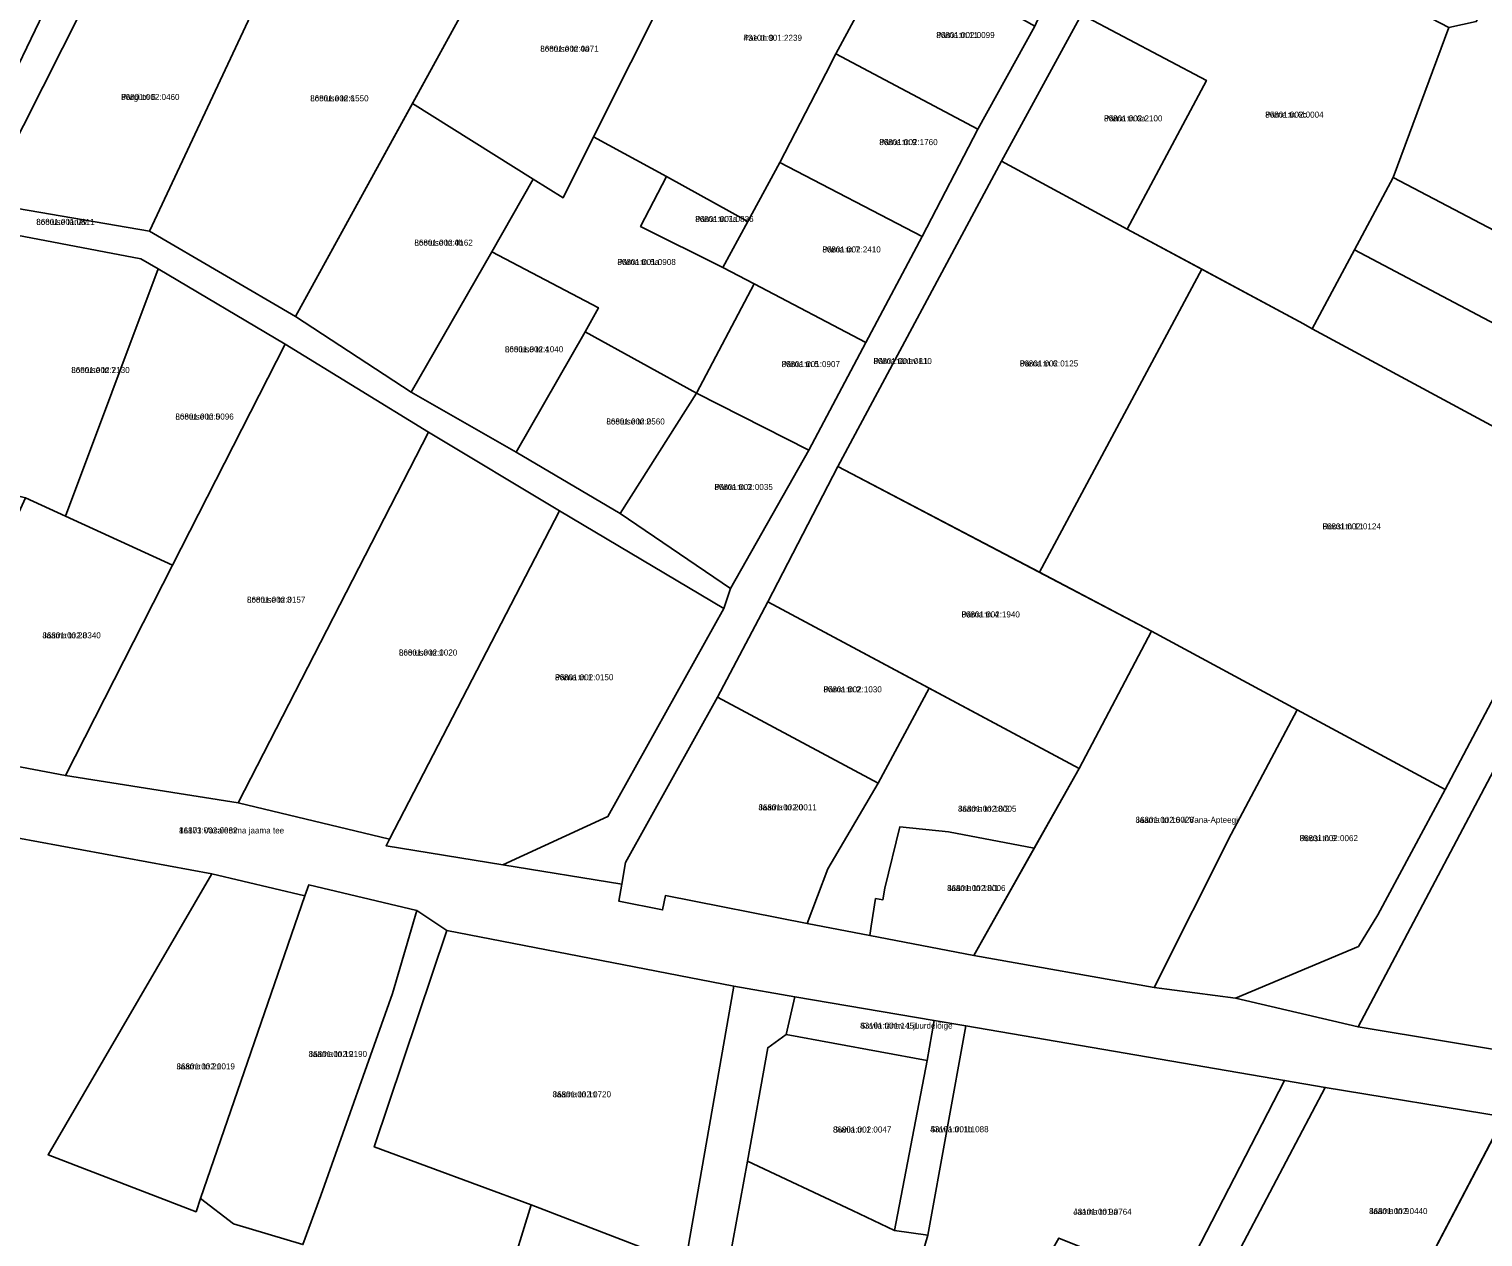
# Model space of a CAD drawing. Extents: x 484607 to 525396, y 6554521 to 6586559.
# Drawn here: x 516301.7 to 516662.8, y 6566598.8 to 6566898.8 of the extents above; entities that cross this region are included whole.
import ezdxf

# ---------------------------------------------------------------- set-up
doc = ezdxf.new("R2010")
doc.units = 0
for name, color, linetype in [('L_AADRESS', 7, 'Continuous'), ('PIIR', 7, 'Continuous'), ('TUNNUS', 7, 'Continuous')]:
    doc.layers.add(name, color=color, linetype=linetype)

msp = doc.modelspace()

# ---------------------------------------------------------------- linework, layer by layer
at = {"layer": 'PIIR'}
for points in [[(516290.5, 6566855.68), (516278.33, 6566857.98), (516282.18, 6566858.75), (516284.92, 6566860.86), (516294.91, 6566881.33), (516311.47, 6566915.84), (516310.19, 6566916.2), (516337.05, 6566972.83), (516342.42, 6566984.14), (516343.49, 6566983.98), (516389.77, 6567083.97), (516398.58, 6567080.56), (516370.04, 6567017.12), (516349.44, 6566970.95), (516343.83, 6566959.05), (516340.8, 6566952.72), (516321.97, 6566913.04), (516319.66, 6566913.38)], [(516448.91, 6566686.41), (516419.34, 6566691.2), (516445.43, 6566703.16), (516474.23, 6566754.86), (516475.84, 6566759.81), (516495.3, 6566794.2), (516509.48, 6566820.94), (516523.5, 6566847.29), (516537.33, 6566873.92), (516551.44, 6566899.57), (516554.36, 6566906.06), (516574.97, 6566943.43), (516595.7, 6566980.41), (516603.41, 6566978.18), (516581.41, 6566937.13), (516563.07, 6566902.41), (516543.2, 6566866.04), (516502.5, 6566790.15), (516485.19, 6566756.57), (516472.67, 6566732.86), (516449.84, 6566691.78)], [(516460.36, 6566909.06), (516477.5, 6566941.11), (516516.4, 6566919.26), (516502.06, 6566892.7), (516499.59, 6566887.8), (516488.12, 6566865.7), (516480.2, 6566851.03), (516460.02, 6566862.16), (516441.87, 6566872.04)], [(516581.41, 6566937.13), (516654.28, 6566899.25), (516640.42, 6566861.91), (516630.88, 6566843.96), (516620.33, 6566824.39), (516618.15, 6566825.57), (516574.43, 6566849.15), (516594.09, 6566886.06), (516563.07, 6566902.41)], [(516654.28, 6566899.25), (516661.08, 6566900.7), (516680.61, 6566937.25), (516717.24, 6566917.86), (516695.46, 6566877.12), (516677.38, 6566842.58), (516640.42, 6566861.91)], [(516367.84, 6566827.44), (516331.58, 6566848.64), (516358.56, 6566906.22), (516369.23, 6566928.83), (516411.41, 6566906.84)], [(516422.67, 6566929.08), (516460.36, 6566909.06), (516441.87, 6566872.04), (516434.28, 6566856.93), (516426.89, 6566861.56), (516396.91, 6566880.36), (516411.41, 6566906.84), (516414.41, 6566912.73)], [(516253.7, 6566891.83), (516268.99, 6566923.91), (516293.21, 6566921.02), (516310.19, 6566916.2), (516311.47, 6566915.84), (516294.91, 6566881.33)], [(516502.06, 6566892.7), (516516.4, 6566919.26), (516551.44, 6566899.57), (516537.33, 6566873.92)], [(516358.56, 6566906.22), (516331.58, 6566848.64), (516290.5, 6566855.68), (516319.66, 6566913.38), (516321.97, 6566913.04)], [(516563.07, 6566902.41), (516594.09, 6566886.06), (516574.43, 6566849.15), (516543.2, 6566866.04)], [(516631.74, 6566650.91), (516601.29, 6566658.08), (516631.85, 6566670.87), (516636.68, 6566678.77), (516653.36, 6566709.91), (516693.09, 6566785.13), (516704.24, 6566805.22), (516713.64, 6566823.3), (516727.86, 6566850.01), (516753.76, 6566898.39), (516761.08, 6566894.66), (516747.01, 6566868.16), (516727.22, 6566830.91), (516713.97, 6566805.98), (516700.94, 6566781.24), (516688.01, 6566756.39), (516674.58, 6566731.94)], [(516488.12, 6566865.7), (516499.59, 6566887.8), (516502.06, 6566892.7), (516537.33, 6566873.92), (516523.5, 6566847.29)], [(516367.84, 6566827.44), (516396.91, 6566880.36), (516426.89, 6566861.56), (516416.59, 6566843.44), (516396.6, 6566808.63)], [(516416.59, 6566843.44), (516426.89, 6566861.56), (516434.28, 6566856.93), (516441.87, 6566872.04), (516460.02, 6566862.16), (516453.53, 6566849.81), (516474.01, 6566839.61), (516481.75, 6566835.49), (516467.47, 6566808.38), (516439.76, 6566823.6), (516443.07, 6566829.59)], [(516474.01, 6566839.61), (516480.2, 6566851.03), (516488.12, 6566865.7), (516523.5, 6566847.29), (516509.48, 6566820.94), (516481.75, 6566835.49)], [(516543.2, 6566866.04), (516574.43, 6566849.15), (516592.97, 6566839.15), (516552.6, 6566763.86), (516502.5, 6566790.15)], [(516453.53, 6566849.81), (516460.02, 6566862.16), (516480.2, 6566851.03), (516474.01, 6566839.61)], [(516640.42, 6566861.91), (516677.38, 6566842.58), (516713.64, 6566823.3), (516704.24, 6566805.22), (516681.92, 6566818.43), (516678.57, 6566820.42), (516677.72, 6566818.98), (516674.54, 6566820.87), (516630.88, 6566843.96)], [(516329.39, 6566841.77), (516333.7, 6566839.22), (516310.7, 6566777.82), (516300.81, 6566782.35), (516290.6, 6566784.81), (516291.21, 6566786.89), (516292.55, 6566787.24), (516293.45, 6566791.08), (516295.36, 6566798.74), (516292.91, 6566809.24), (516293.7, 6566812.42), (516291.26, 6566813.14), (516292.58, 6566819.08), (516298.6, 6566847.64)], [(516416.59, 6566843.44), (516443.07, 6566829.59), (516439.76, 6566823.6), (516422.63, 6566793.73), (516396.6, 6566808.63)], [(516630.88, 6566843.96), (516674.54, 6566820.87), (516677.72, 6566818.98), (516678.57, 6566820.42), (516681.92, 6566818.43), (516704.24, 6566805.22), (516693.09, 6566785.13), (516620.33, 6566824.39)], [(516333.7, 6566839.22), (516365.31, 6566820.52), (516337.32, 6566765.6), (516310.7, 6566777.82)], [(516592.97, 6566839.15), (516618.15, 6566825.57), (516620.33, 6566824.39), (516693.09, 6566785.13), (516653.36, 6566709.91), (516616.63, 6566729.74), (516580.47, 6566749.24), (516552.6, 6566763.86)], [(516467.47, 6566808.38), (516481.75, 6566835.49), (516509.48, 6566820.94), (516495.3, 6566794.2)], [(516467.47, 6566808.38), (516448.48, 6566778.46), (516422.63, 6566793.73), (516439.76, 6566823.6)], [(516365.31, 6566820.52), (516400.87, 6566798.65), (516353.64, 6566706.61), (516310.71, 6566713.38), (516337.32, 6566765.6)], [(516475.84, 6566759.81), (516448.48, 6566778.46), (516467.47, 6566808.38), (516495.3, 6566794.2)], [(516400.87, 6566798.65), (516433.4, 6566779.13), (516391.18, 6566697.54), (516353.64, 6566706.61)], [(516562.46, 6566715.14), (516485.19, 6566756.57), (516502.5, 6566790.15), (516580.47, 6566749.24)], [(516337.32, 6566765.6), (516310.71, 6566713.38), (516272.63, 6566720.63), (516273.54, 6566722.61), (516300.81, 6566782.35), (516310.7, 6566777.82)], [(516474.23, 6566754.86), (516445.43, 6566703.16), (516419.34, 6566691.2), (516390.34, 6566695.92), (516391.18, 6566697.54), (516433.4, 6566779.13)], [(516485.19, 6566756.57), (516525.21, 6566735.11), (516512.53, 6566711.5), (516472.67, 6566732.86)], [(516616.63, 6566729.74), (516600.19, 6566698.81), (516581.07, 6566660.76), (516536.31, 6566668.71), (516562.46, 6566715.14), (516580.47, 6566749.24)], [(516500.06, 6566690.2), (516512.53, 6566711.5), (516525.21, 6566735.11), (516562.46, 6566715.14), (516551.32, 6566695.37), (516530, 6566699.37), (516517.95, 6566700.64), (516514.18, 6566685.42), (516513.72, 6566682.52), (516511.91, 6566682.81), (516510.81, 6566675.93), (516510.45, 6566673.67), (516494.89, 6566676.65)], [(516512.53, 6566711.5), (516500.06, 6566690.2), (516494.89, 6566676.65), (516459.71, 6566683.57), (516459.01, 6566680.01), (516448.18, 6566682.14), (516448.91, 6566686.41), (516449.84, 6566691.78), (516472.67, 6566732.86)], [(516712.86, 6566711.63), (516706.02, 6566699), (516705.26, 6566699.39), (516676.68, 6566643.47), (516631.74, 6566650.91), (516674.58, 6566731.94)], [(516616.63, 6566729.74), (516653.36, 6566709.91), (516636.68, 6566678.77), (516631.85, 6566670.87), (516601.29, 6566658.08), (516581.07, 6566660.76), (516600.19, 6566698.81)], [(516536.31, 6566668.71), (516510.45, 6566673.67), (516510.81, 6566675.93), (516511.91, 6566682.81), (516513.72, 6566682.52), (516514.18, 6566685.42), (516517.95, 6566700.64), (516530, 6566699.37), (516551.32, 6566695.37)], [(516370.19, 6566683.5), (516344.25, 6566608.32), (516343.14, 6566605.01), (516306.39, 6566619.19), (516347.09, 6566688.95)], [(516397.98, 6566679.87), (516391.91, 6566659.2), (516374.17, 6566609.04), (516369.68, 6566596.85), (516352.41, 6566602.02), (516344.25, 6566608.32), (516370.19, 6566683.5), (516371.12, 6566686.19)], [(516476.68, 6566661.02), (516464.65, 6566592.02), (516426.41, 6566606.7), (516387.41, 6566621.11), (516405.45, 6566674.88)], [(516491.88, 6566658.39), (516526.45, 6566652.51), (516524.74, 6566642.6), (516489.67, 6566649.01)], [(516534.34, 6566651.16), (516524.85, 6566599.21), (516516.62, 6566600.37), (516524.74, 6566642.6), (516526.45, 6566652.51)], [(516516.62, 6566600.37), (516506.18, 6566605.33), (516480.06, 6566617.55), (516485.11, 6566645.77), (516489.67, 6566649.01), (516524.74, 6566642.6)], [(516524.85, 6566599.21), (516534.34, 6566651.16), (516613.48, 6566637.62), (516587.11, 6566586.51), (516557.39, 6566598.45), (516553.9, 6566592.27), (516537.14, 6566560.84), (516535.6, 6566557.36), (516515.51, 6566566.91)], [(516532.44, 6566464.05), (516524.29, 6566467.04), (516565.87, 6566545.03), (516582.88, 6566576.82), (516587.11, 6566586.51), (516613.48, 6566637.62), (516623.59, 6566635.89), (516600.94, 6566592.98), (516562.86, 6566518.16), (516551.94, 6566498.86)], [(516668.04, 6566628.55), (516638.62, 6566572.52), (516600.94, 6566592.98), (516623.59, 6566635.89)], [(516715.37, 6566623.3), (516676.49, 6566552.95), (516638.62, 6566572.52), (516669.65, 6566631.63)], [(516480.06, 6566617.55), (516506.18, 6566605.33), (516516.62, 6566600.37), (516524.85, 6566599.21), (516515.51, 6566566.91), (516513.87, 6566567.67), (516476.26, 6566586.79), (516474.81, 6566587.09), (516475.56, 6566592.77)], [(516414.58, 6566568.67), (516426.41, 6566606.7), (516464.65, 6566592.02), (516458.15, 6566552.93)]]:
    msp.add_lwpolyline(points, close=True, dxfattribs=at)
for points in [[(516290.5, 6566855.68), (516331.58, 6566848.64), (516367.84, 6566827.44), (516396.6, 6566808.63), (516422.63, 6566793.73), (516448.48, 6566778.46), (516475.84, 6566759.81), (516474.23, 6566754.86), (516433.4, 6566779.13), (516400.87, 6566798.65), (516365.31, 6566820.52), (516333.7, 6566839.22), (516329.39, 6566841.77), (516298.6, 6566847.64)], [(516272.63, 6566720.63), (516310.71, 6566713.38), (516353.64, 6566706.61), (516391.18, 6566697.54), (516390.34, 6566695.92), (516419.34, 6566691.2), (516448.91, 6566686.41), (516448.18, 6566682.14), (516459.01, 6566680.01), (516459.71, 6566683.57), (516494.89, 6566676.65), (516510.45, 6566673.67), (516536.31, 6566668.71), (516581.07, 6566660.76), (516601.29, 6566658.08), (516631.74, 6566650.91), (516676.68, 6566643.47)], [(516841.78, 6566597.63), (516812.41, 6566603.04), (516800.32, 6566605.27), (516714.17, 6566621.13), (516715.37, 6566623.3), (516669.65, 6566631.63), (516668.04, 6566628.55), (516623.59, 6566635.89), (516613.48, 6566637.62), (516534.34, 6566651.16), (516526.45, 6566652.51), (516491.88, 6566658.39), (516476.68, 6566661.02), (516405.45, 6566674.88), (516397.98, 6566679.87), (516371.12, 6566686.19), (516370.19, 6566683.5), (516347.09, 6566688.95), (516287.75, 6566699.91)], [(516287.75, 6566699.91), (516347.09, 6566688.95), (516306.39, 6566619.19), (516343.14, 6566605.01), (516344.25, 6566608.32), (516352.41, 6566602.02), (516369.68, 6566596.85), (516374.17, 6566609.04), (516391.91, 6566659.2), (516397.98, 6566679.87), (516405.45, 6566674.88), (516387.41, 6566621.11), (516426.41, 6566606.7), (516414.58, 6566568.67), (516401.53, 6566528.92), (516381.14, 6566533.25), (516367.98, 6566553.24), (516323.18, 6566539.6), (516323.16, 6566533.18), (516288.85, 6566519.72)], [(516464.65, 6566592.02), (516476.68, 6566661.02), (516491.88, 6566658.39), (516489.67, 6566649.01), (516485.11, 6566645.77), (516480.06, 6566617.55), (516475.56, 6566592.77)]]:
    msp.add_lwpolyline(points, dxfattribs=at)

# ---------------------------------------------------------------- texts
at = {"layer": 'L_AADRESS'}
for s, p in [('Pae tn 9', (516479.13, 6566895.9)), ('Pärna tn 11', (516526.98, 6566896.59)), ('Lootuse tn 4a', (516428.63, 6566893.19)), ('Pargi tn 6', (516324.53, 6566881.21)), ('Lootuse tn 6', (516371.49, 6566880.87)), ('Pärna tn 6a', (516568.65, 6566875.88)), ('Pärna tn 6b', (516608.68, 6566876.82)), ('Pärna tn 9', (516512.82, 6566869.99)), ('Lootuse tänav', (516303.45, 6566850.17)), ('Pärna tn 7a', (516467.11, 6566850.88)), ('Lootuse tn 4b', (516397.37, 6566845.02)), ('Pärna tn 7', (516498.7, 6566843.32)), ('Pärna tn 5a', (516447.79, 6566840.21)), ('Lootuse tn 4', (516419.84, 6566818.54)), ('Lootuse tn 7', (516312.15, 6566813.37)), ('Pärna tn 5', (516488.56, 6566814.84)), ('Pärna tänav L1', (516511.38, 6566815.6)), ('Pärna tn 6', (516547.73, 6566815)), ('Lootuse tn 5', (516338.01, 6566801.81)), ('Lootuse tn 2', (516445.05, 6566800.59)), ('Pärna tn 3', (516471.89, 6566784.32)), ('Roosi tn 11', (516622.91, 6566774.53)), ('Lootuse tn 3', (516355.79, 6566756.32)), ('Pärna tn 4', (516533.25, 6566752.65)), ('Jaama tn 28', (516304.98, 6566747.46)), ('Lootuse tn 1', (516393.52, 6566743.19)), ('Pärna tn 1', (516432.29, 6566737.05)), ('Pärna tn 2', (516498.96, 6566734.04)), ('Jaama tn 20', (516482.82, 6566704.75)), ('Jaama tn 18/2', (516532.39, 6566704.39)), ('Jaama tn 16 // Vana-Apteegi', (516576.47, 6566701.62)), ('11173 Vasalemma jaama tee', (516338.93, 6566698.99)), ('Roosi tn 9', (516617.21, 6566697.08)), ('Jaama tn 18/1', (516529.68, 6566684.68)), ('Suvila tänav 1 juurdelõige', (516508.06, 6566650.5)), ('Jaama tn 19', (516371.11, 6566643.46)), ('Jaama tn 21', (516338.29, 6566640.37)), ('Jaama tn 11', (516431.71, 6566633.45)), ('Suvila tn 1b', (516525.48, 6566624.77)), ('Suvila tn 1', (516501.32, 6566624.69)), ('Jaama tn 9a', (516561.02, 6566604.26)), ('Jaama tn 9', (516634.49, 6566604.43))]:
    msp.add_text(s, height=1.5, dxfattribs=at).set_placement(p)
at = {"layer": 'TUNNUS'}
for s, p in [('43101:001:2239', (516479.13, 6566895.9)), ('86801:002:0099', (516526.98, 6566896.59)), ('86801:002:0071', (516428.63, 6566893.19)), ('86801:002:0460', (516324.53, 6566881.21)), ('86801:002:1550', (516371.49, 6566880.87)), ('86801:002:2100', (516568.65, 6566875.88)), ('86801:002:0004', (516608.68, 6566876.82)), ('86801:002:1760', (516512.82, 6566869.99)), ('86801:001:0811', (516303.45, 6566850.17)), ('86801:001:0836', (516467.11, 6566850.88)), ('86801:002:0162', (516397.37, 6566845.02)), ('86801:002:2410', (516498.7, 6566843.32)), ('86801:001:0908', (516447.79, 6566840.21)), ('86801:002:1040', (516419.84, 6566818.54)), ('86801:002:2130', (516312.15, 6566813.37)), ('86801:001:0907', (516488.56, 6566814.84)), ('86801:001:0810', (516511.38, 6566815.6)), ('86801:002:0125', (516547.73, 6566815)), ('86801:002:0096', (516338.01, 6566801.81)), ('86801:002:0560', (516445.05, 6566800.59)), ('86801:002:0035', (516471.89, 6566784.32)), ('86801:002:0124', (516622.91, 6566774.53)), ('86801:002:0157', (516355.79, 6566756.32)), ('86801:002:1940', (516533.25, 6566752.65)), ('86801:002:0340', (516304.98, 6566747.46)), ('86801:002:0020', (516393.52, 6566743.19)), ('86801:002:0150', (516432.29, 6566737.05)), ('86801:002:1030', (516498.96, 6566734.04)), ('86801:002:0011', (516482.82, 6566704.75)), ('86801:002:0005', (516532.39, 6566704.39)), ('86801:002:0028', (516576.47, 6566701.62)), ('86801:002:0082', (516338.93, 6566698.99)), ('86801:002:0062', (516617.21, 6566697.08)), ('86801:002:0006', (516529.68, 6566684.68)), ('43101:001:1451', (516508.06, 6566650.5)), ('86801:002:2190', (516371.11, 6566643.46)), ('86801:002:0019', (516338.29, 6566640.37)), ('86801:002:0720', (516431.71, 6566633.45)), ('86801:002:0047', (516501.32, 6566624.69)), ('43101:001:1088', (516525.48, 6566624.77)), ('43101:001:0764', (516561.02, 6566604.26)), ('86801:002:0440', (516634.49, 6566604.43))]:
    msp.add_text(s, height=1.5, dxfattribs=at).set_placement(p)

doc.saveas('drawing.dxf')
